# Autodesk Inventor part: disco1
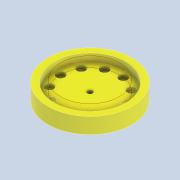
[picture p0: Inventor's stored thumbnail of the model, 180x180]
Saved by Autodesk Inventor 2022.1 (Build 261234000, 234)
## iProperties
Created: 2022-04
Part Number: disco1
Material: Generico
Document SubType Name: Modeling
Designer: i911900
Density: 1 g/cm^3
Appearance: Giallo
Author: i911900
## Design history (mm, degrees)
sketch "Schizzo1"
  geometry: C1 r 40 at (0, 0); 1 further point
  constraints: 1 centre point, 1 coincident
  dimensions: "d0" = 80 diameter of C1
extrude "Estrusione1" new body sketch "Schizzo1" distance "d1" = 15; taper "d2" = 0 deg
sketch "Schizzo2"
  geometry: C1 r 34 at (0, 0); 1 further point
  constraints: 1 centre point, 1 coincident
  dimensions: "d3" = 68 diameter of C1
extrude "Estrusione2" cut sketch "Schizzo2" distance "d4" = 8; taper "d5" = 0 deg
sketch "Schizzo3"
  geometry: C1 r 2.5 at (0, 0); 1 further point
  constraints: 1 centre point, 1 coincident
  dimensions: "d6" = 5 diameter of C1
extrude "Estrusione3" cut sketch "Schizzo3" extent not by distance; stored distance "d7" = 0; taper "d8" = 0 deg
sketch "Schizzo4" dims "d9" = 56
  geometry: C1 r 4 at (-28, 0); 2 further points
  constraints: 1 centre point, 1 coincident, 1 horizontal alignment, 2 other
  dimensions: "d10" = 8 diameter of C1
extrude "Estrusione4" cut sketch "Schizzo4" distance "d11" = 4; taper "d12" = 0 deg
pattern_circular "Serie circolare1" dims angle "d14" = 360 deg
sketch "Schizzo5"
  geometry: C1 r 4 at (3.985, 27.715) reference; 2 further points
  constraints: 1 coincident, 3 other
feature "SupEstrusione1" sketch "Schizzo5" dims "d16" = 10, "d17" = 0
node "Solido1"
node "Superf1"
